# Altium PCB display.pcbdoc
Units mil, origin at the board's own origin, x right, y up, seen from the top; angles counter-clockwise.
Board outline 6129.92 x 2541.69 mil, 2 copper layers (Top Layer, Bottom Layer); 54 components, 77 nets, 200 pads, 30 vias.
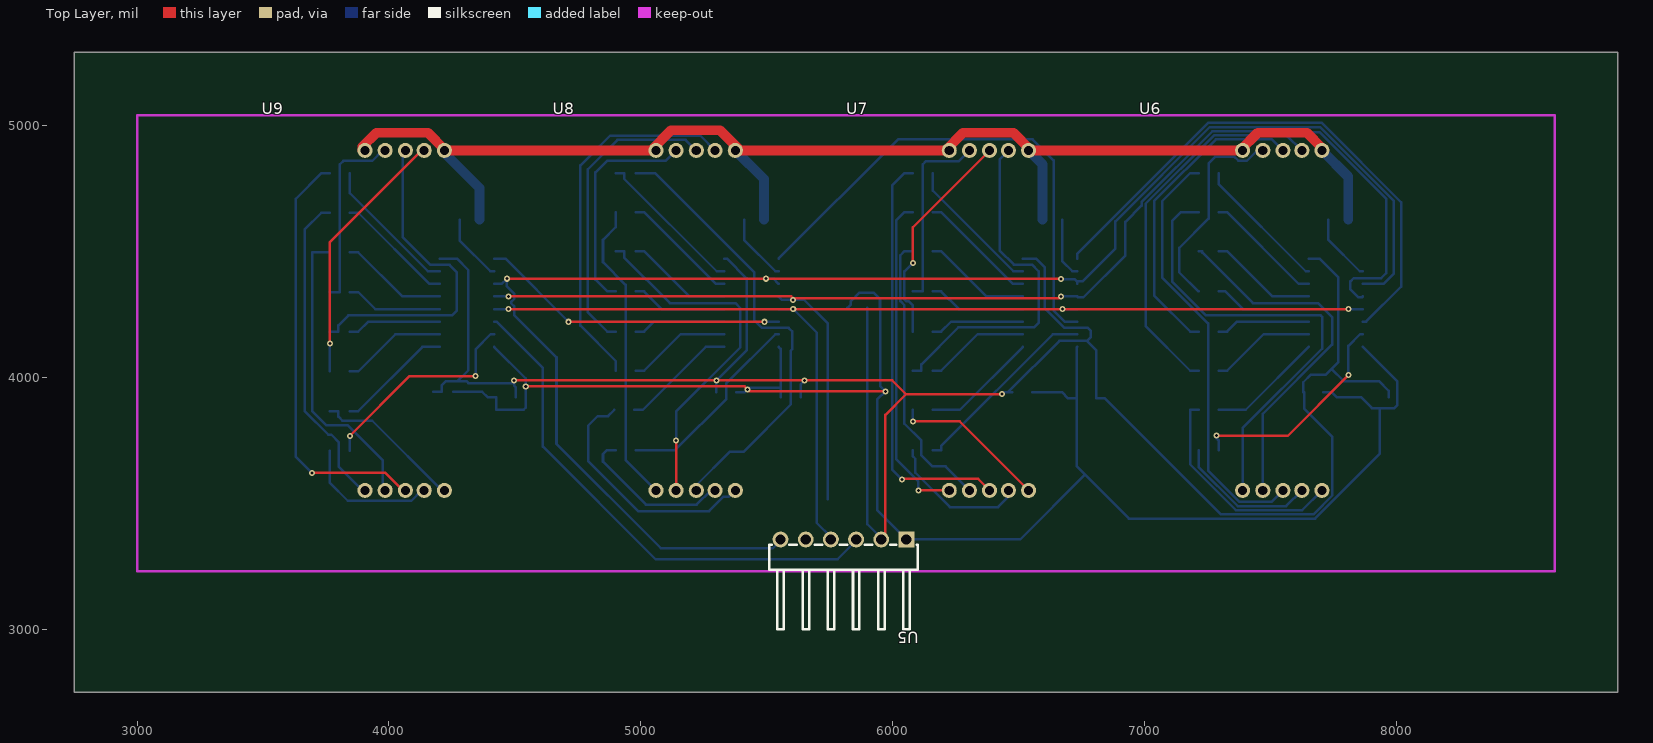
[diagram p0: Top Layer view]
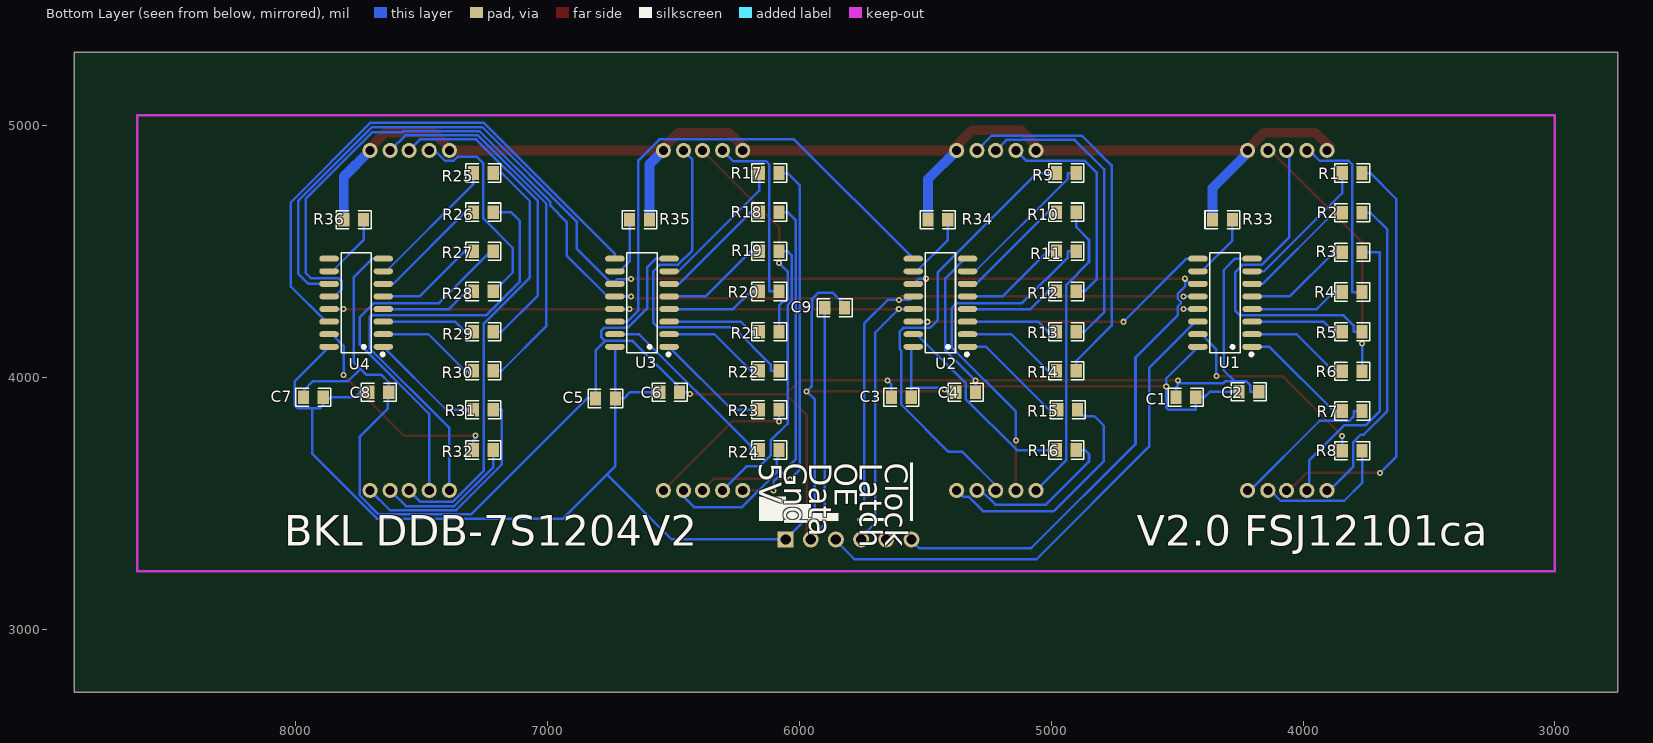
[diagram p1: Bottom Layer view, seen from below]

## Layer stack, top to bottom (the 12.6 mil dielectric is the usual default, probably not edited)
Top Layer: signal copper (thickness not stored)
Dielectric: dielectric 12.6, FR-4, Dk 4.8
Bottom Layer: signal copper (thickness not stored)

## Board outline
8879.92,2750 2750,2750 2750,5291.69 8879.92,5291.69

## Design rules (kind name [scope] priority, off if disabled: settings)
BoardOutlineClearance safeClearance [All] p0: genericclearance=10 ignorepadtopadclearanceinfootprint=FALSE except(0: Arc-SplitContinuation Track-SplitContinuation SMDPad-SplitContinuation THPad-SplitContinuation Via-SplitContinuation Fill-SplitContinuation Poly-SplitContinuation Region-SplitContinuation Text-SplitContinuation; 6: Track-CutoutEdge SMDPad-CutoutEdge THPad-CutoutEdge Via-CutoutEdge Fill-CutoutEdge Region-CutoutEdge; 11.8: Track-OutlineEdge SMDPad-OutlineEdge THPad-OutlineEdge Via-OutlineEdge Fill-OutlineEdge Region-OutlineEdge Poly-OutlineEdge Text-OutlineEdge)
Clearance safeClearance [(InNet('$1N6011') OR InNet('$1N6122') OR InNet('$1N6177') OR InNet('$1N6264') OR InNet('$1N6089') OR InNet('$1N6486') OR InNet('$1N6506') OR InNet('GND') OR InNet('VCC') OR InNet('$1N2299') OR InNet('$1N2304') OR InNet('$1N2303') OR InNet('$1N2305') OR InNet('$1N2301') OR InNet('$1N2297') OR InNet('$1N41012') OR InNet('$1N40781') OR InNet('$1N41044') OR InNet('$1N40619') OR InNet('$1N40652') OR InNet('$1N41427') OR InNet('$1N41428') OR InNet('$1N41338') OR InNet('$1N45600') OR InNet('$1N45601') OR InNet('$1N45602') OR InNet('$1N45596') OR InNet('$1N45606') OR InNet('$1N45595') OR InNet('$1N45598') OR InNet('$1N45607') OR InNet('$1N45594') OR InNet('$1N45609') OR InNet('$1N45599') OR InNet('$1N45603') OR InNet('$1N45597') OR InNet('$1N45604') OR InNet('$1N46576') OR InNet('$1N46577') OR InNet('$1N46584') OR InNet('$1N46585') OR InNet('$1N47561') OR InNet('$1N47562') OR InNet('$1N47571') OR InNet('$1N47559') OR InNet('$1N52982') OR InNet('$1N53020') OR InNet('$1N45593') OR InNet('$1N47985') OR InNet('$1N45605') OR InNet('$1N46581') OR InNet('$1N46582') OR InNet('$1N46583') OR InNet('$1N46587') OR InNet('$1N46579') OR InNet('$1N46588') OR InNet('$1N46575') OR InNet('$1N46590') OR InNet('$1N46580') OR InNet('$1N46578') OR InNet('$1N46574') OR InNet('$1N46586') OR InNet('$1N47566') OR InNet('$1N47567') OR InNet('$1N47568') OR InNet('$1N47572') OR InNet('$1N47564') OR InNet('$1N47573') OR InNet('$1N47560') OR InNet('$1N47575') OR InNet('$1N47565') OR InNet('$1N47569') OR InNet('$1N47563') OR InNet('$1N47570') OR InNet('$1N48013') OR InNet('$1N2302') OR InNet('$1N57025'))] p1: gap=7 ignorepadtopadclearanceinfootprint=FALSE except(6: Track-Track Track-SMDPad SMDPad-SMDPad Track-THPad SMDPad-THPad THPad-THPad Track-Via SMDPad-Via THPad-Via Via-Via Track-Fill SMDPad-Fill THPad-Fill Via-Fill Fill-Fill Track-Region SMDPad-Region THPad-Region Via-Region Fill-Region Region-Region Track-Poly SMDPad-Poly THPad-Poly Via-Poly Fill-Poly Region-Poly Poly-Poly Track-Text SMDPad-Text THPad-Text Via-Text Fill-Text Region-Text Poly-Text Text-Text Track-Hole SMDPad-Hole THPad-Hole Via-Hole Fill-Hole Region-Hole Poly-Hole Text-Hole; 11.8: Track-Sheet SMDPad-Sheet THPad-Sheet Via-Sheet Fill-Sheet Region-Sheet Poly-Sheet Text-Sheet Sheet-Hole)
DiffPairsRouting differentialPair [All] p1: maxuncoupledlength=10 minlimit=6 maxlimit=6 mostfreqgap=6 toplayer_minwidth=5 toplayer_prefwidth=10 toplayer_maxwidth=100 bottomlayer_minwidth=5 bottomlayer_prefwidth=10 bottomlayer_maxwidth=100
PasteMaskExpansion pasteMaskExpansion [All] p1: expansion=0
PlaneConnect innerPlane [All] p1: planeconnectstyle=Relief reliefexpansion=20 reliefentries=4 reliefconductorwidth=10 reliefairgap=10
PolygonConnect copperRegion [All] p1: connectstyle=Relief reliefentries=4 reliefconductorwidth=10 polygonreliefangle="90 Angle" airgapwidth=10
RoutingVias viaSize [All] p1: viastyle="Through Hole" holewidth=12.0078 minholewidth=11.811 maxholewidth=236.2204 width=24.0158 minwidth=19.685 maxwidth=393.7008
SolderMaskExpansion solderMaskExpansion [All] p1: useseparateexpansions=TRUE expansion=2 expansionbottom=2
Width trackWidth [All] p1: maxlimit=100 minlimit=5 preferedwidth=10
Width Vcc [All] p1: maxlimit=100 minlimit=24 preferedwidth=39

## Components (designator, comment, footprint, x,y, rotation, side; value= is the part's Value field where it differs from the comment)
C1 "CR0805J80221G" R0805 4465,3921.69 r0 bottom
C2 "CR0805J80221G" R0805 4215,3943.05 r180 bottom
C3 "CR0805J80221G" R0805 5595,3921.69 r0 bottom
C4 "CR0805J80221G" R0805 5340,3941.69 r180 bottom
C5 "CR0805J80221G" R0805 6770,3916.69 r0 bottom
C6 "CR0805J80221G" R0805 6515,3941.69 r180 bottom
C7 "CR0805J80221G" R0805 7930,3921.69 r0 bottom
C8 "CR0805J80221G" R0805 7670,3941.69 r180 bottom
C9 "CR0805J80221G" R0805 5860,4276.69 r0 bottom
R1 "CR0805J80271G" R0805 3805,4811.69 r0 bottom
R2 "CR0805J80221G" R0805 3805,4654.21 r0 bottom
R3 "CR0805J80221G" R0805 3805,4496.73 r0 bottom
R4 "CR0805J80221G" R0805 3805,4339.25 r0 bottom
R5 "CR0805J80221G" R0805 3805,4181.77 r0 bottom
R6 "CR0805J80221G" R0805 3805,4024.29 r0 bottom
R7 "CR0805J80221G" R0805 3805,3866.81 r0 bottom
R8 "CR0805J80221G" R0805 3805,3709.33 r0 bottom
R9 "CR0805J80271G" R0805 4940,4811.69 r180 bottom
R10 "CR0805J80221G" R0805 4940,4656.69 r0 bottom
R11 "CR0805J80221G" R0805 4940,4501.69 r0 bottom
R12 "CR0805J80221G" R0805 4940,4341.69 r0 bottom
R13 "CR0805J80221G" R0805 4940,4181.69 r0 bottom
R14 "CR0805J80221G" R0805 4940,4026.69 r0 bottom
R15 "CR0805J80221G" R0805 4935,3871.69 r0 bottom
R16 "CR0805J80221G" R0805 4940,3711.69 r0 bottom
R17 "CR0805J80271G" R0805 6120,4811.69 r0 bottom
R18 "CR0805J80221G" R0805 6120,4656.69 r0 bottom
R19 "CR0805J80221G" R0805 6120,4501.69 r0 bottom
R20 "CR0805J80221G" R0805 6120,4341.69 r0 bottom
R21 "CR0805J80221G" R0805 6120,4181.69 r0 bottom
R22 "CR0805J80221G" R0805 6120,4026.69 r0 bottom
R23 "CR0805J80221G" R0805 6120,3871.69 r0 bottom
R24 "CR0805J80221G" R0805 6120,3711.69 r0 bottom
R25 "CR0805J80271G" R0805 7255,4811.69 r0 bottom
R26 "CR0805J80221G" R0805 7255,4656.69 r0 bottom
R27 "CR0805J80221G" R0805 7255,4501.69 r0 bottom
R28 "CR0805J80221G" R0805 7255,4341.69 r0 bottom
R29 "CR0805J80221G" R0805 7255,4181.69 r0 bottom
R30 "CR0805J80221G" R0805 7255,4026.69 r0 bottom
R31 "CR0805J80221G" R0805 7255,3871.69 r0 bottom
R32 "CR0805J80221G" R0805 7255,3711.69 r0 bottom
R33 "CR0805F81002G" R0805 4320,4626.69 r0 bottom
R34 "CR0805F81002G" R0805 5450,4626.69 r0 bottom
R35 "CR0805F81002G" R0805 6635,4626.69 r180 bottom
R36 "CR0805F81002G" R0805 7770,4626.69 r0 bottom
U1 "74HC595D,118" SOIC-16_L9.9-W3.9-P1.27-LS6.0-BL 4310,4296.69 r90 bottom
U2 "74HC595D,118" SOIC-16_L9.9-W3.9-P1.27-LS6.0-BL 5440,4296.69 r90 bottom
U3 "74HC595D,118" SOIC-16_L9.9-W3.9-P1.27-LS6.0-BL 6625,4296.69 r90 bottom
U4 "74HC595D,118" SOIC-16_L9.9-W3.9-P1.27-LS6.0-BL 7760,4296.69 r90 bottom
U5 "P125-1106A0BR138A1" HDR-TH_6P-P2.54-H-M_P125-1106A0BR138A1 5805,3356.69 r180 top
U6 "FJS12101" FJS12101 7550,4226.69 r0 top
U7 "FJS12101" FJS12101 6385,4226.69 r0 top
U8 "FJS12101" FJS12101 5220.32,4226.69 r0 top
U9 "FJS12101" FJS12101 4065,4226.69 r0 top

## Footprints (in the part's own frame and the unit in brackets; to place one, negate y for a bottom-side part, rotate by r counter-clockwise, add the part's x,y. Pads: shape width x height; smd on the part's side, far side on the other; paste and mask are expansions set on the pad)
FJS12101 [mil]
  round 60 hole 36: 1(-160,675) 2(-80,675) 3(0,675) 4(75,675) 5(155,675) 6(155,-675) 7(75,-675) 8(0,-675) 9(-80,-675) 10(-160,-675)
HDR-TH_6P-P2.54-H-M_P125-1106A0BR138A1 [mm]
  rect 1.6x1.6 hole 1.05: 1(-6.35,0)
  round 1.6 hole 1.05: 2(-3.81,0) 3(-1.27,0) 4(1.27,0) 5(3.81,0) 6(6.35,0)
  silkscreen extent -7.47,0.51 7.51,9.06
R0805 [mm]
  rect 1.133x1.377 smd: 1(-1,0) 2(1,0)
  silkscreen extent -1.76,-0.92 1.76,0.92
SOIC-16_L9.9-W3.9-P1.27-LS6.0-BL [mil]
  oval 23.7x77.6 smd: 1(-175,-107.7) 2(-125,-107.7) 3(-75,-107.7) 4(-25,-107.7) 5(25,-107.7) 6(75,-107.7) 7(125,-107.7) 8(175,-107.7) 9(175,107.7) 10(125,107.7) 11(75,107.7) 12(25,107.7) 13(-25,107.7) 14(-75,107.7) 15(-125,107.7) 16(-175,107.7)
  silkscreen extent -211,-111 198,60

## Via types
v1: diameter 24, hole 12, Top Layer to Bottom Layer, 30 vias

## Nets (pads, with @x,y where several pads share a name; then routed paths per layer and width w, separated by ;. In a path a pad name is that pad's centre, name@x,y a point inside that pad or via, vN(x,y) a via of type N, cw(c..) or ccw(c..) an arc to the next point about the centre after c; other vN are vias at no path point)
$1N2297: U1.9 U2.14 | length 1234
  Top Layer w10: v1(4713.6,4221.17) v1(5490.7,4221.17)
  Bottom Layer w10: U1.9 4463.1,4471.67 v1(4713.6,4221.17) ; v1(5490.7,4221.17) 5547.2,4221.17 U2.14
$1N2299: R8.2 U1.15 | length 861.2
  Top Layer w10: v1(3844.4,3767.17) 4082.3,4005.07 v1(4343.7,4005.07)
  Bottom Layer w10: R8.2@3844.4,3709.37 v1(3844.4,3767.17) ; v1(4343.7,4005.07) 4343.7,4111.87 4403.5,4171.67 U1.15
$1N2301: R33.1 U1.10 | length 270.6
  Bottom Layer w10: R33.1 4280.6,4543.67 4402.6,4421.67 U1.10
$1N2302: U1.13 U2.13 U3.13 U4.13 U5.4 | length 4536
  Top Layer w10: v1(4475.2,4271.67) v1(5605.4,4271.67) v1(6675,4271.67) v1(7809.7,4271.67)
  Bottom Layer w10: U1.13 v1(4475.2,4271.67) ; U2.13 v1(5605.4,4271.67) 5698.7,4178.37 5698.7,3422.73 U5.4@5757.37,3364.06 ; v1(6675,4271.67) U3.13 ; v1(7809.7,4271.67) U4.13
$1N2303: U1.12 U2.12 U3.12 U4.12 U5.5 | length 5512.6
  Top Layer w10: v1(4475.1,4322.07) 5596.9,4322.07 v1@5604.2,4314.77 ; v1(5604.2,4307.87) v1@5604.2,4314.77 ; v1(6669.1,4321.77) 6662.2,4314.77 v1@5604.2,4314.77
  Bottom Layer w10: U1.12 4418.1,4322.07 v1(4475.1,4322.07) ; U2.12 5561.5,4307.87 v1(5604.2,4307.87) 5649.2,4307.87 5743,4214.07 5743,3516.69 ; v1(6669.1,4321.77) 6732.7,4321.77 6736.77,4317.7 6757.06,4317.7 6924.56,4485.15 6924.56,4617.9 6989,4682.33 6989,4696.6 7270.07,4977.67 7571.63,4977.67 7575.2,4974.1 7695.74,4974.1 7960,4709.84 7960,4413.97 7940.57,4394.54 7831.29,4394.54 7817.9,4381.16 7817.9,4349.38 7849.59,4317.7 7863.73,4317.7 U4.12
$1N2304: U1.14 U5.3 | length 2027.7
  Bottom Layer w10: U1.14 4427.8,4221.67 4611.2,4038.17 4611.2,3725.49 5058.72,3277.97 5781.28,3277.97 U5.3@5844.98,3341.67
$1N2305: U1.11 U2.11 U3.11 U4.11 U5.6 | length 6330.4
  Top Layer w10: v1(4468,4392.07) v1(5497.1,4392.07) 6668,4392.07 v1(6669.1,4390.87)
  Bottom Layer w10: U1.11 4447.6,4371.67 v1(4468,4392.07) 4468,4361.7 4498.1,4331.6 4498.1,4312.54 4484.73,4299.17 4484.73,4294.67 4498.2,4281.2 4498.2,4246.77 4665.3,4079.67 4665.3,3736.17 5079.8,3321.67 5524.98,3321.67 U5.6@5544.98,3341.67 ; v1(5497.1,4392.07) 5527.3,4392.07 U2.11 ; v1(6669.1,4390.87) 6723.1,4390.87 U3.11@6732.7,4381.27 ; U3.11 U3.11@6732.7,4381.27 ; U4.11 7949.98,4371.67 7990,4411.69 7990,4702.47 7698,4994.47 7259.4,4994.47 6885,4619.88 6885,4511.57 6754.7,4381.27 U3.11@6732.7,4381.27
$1N6011: R7.2 U1.1 | length 463.5
  Bottom Layer w10: R7.2 3878,3866.77 4132.9,4121.67 U1.1
$1N6089: R3.2 U1.5 | length 430.4
  Bottom Layer w10: R3.2@3844.4,4496.77 3878,4496.77 4053.1,4321.67 U1.5
$1N6122: R6.2 U1.2 | length 419
  Bottom Layer w10: R6.2 3878,4024.27 4025.4,4171.67 U1.2
$1N6177: R5.2 U1.3 | length 374.4
  Bottom Layer w10: R5.2 3878,4181.77 3917.9,4221.67 U1.3
$1N6264: R4.2 U1.4 | length 385.9
  Bottom Layer w10: R4.2 3878,4339.27 3945.6,4271.67 U1.4
$1N6486: R2.2 U1.6 | length 474.9
  Bottom Layer w10: R2.2 3878,4654.17 4160.5,4371.67 U1.6
$1N6506: R1.2 U1.7 | length 565.9
  Bottom Layer w10: R1.2 3844.4,4732.29 4155.02,4421.67 U1.7
$1N40619: R8.1 U9.7 | length 539.1
  Bottom Layer w10: R8.1@3765.6,3709.37 3765.6,3581.09 3836.32,3510.37 4088.7,3510.37 U9.7@4130,3551.67
$1N40652: R7.1 U9.6 | length 588.1
  Bottom Layer w10: R7.1 3799.2,3866.77 3799.2,3844.17 3815.5,3827.97 3933.7,3827.97 U9.6@4210,3551.67
$1N40781: R3.1 U9.9 | length 1181.9
  Bottom Layer w10: R3.1@3765.6,4496.77 3695,4496.77 3695,3866.17 3751.4,3809.77 3837.2,3809.77 3975,3671.97 U9.9@3975,3551.67
$1N41012: R2.1 U9.10 | length 1266
  Bottom Layer w10: R2.1 3732,4654.17 3665,4587.17 3665,3866.97 3759.6,3772.37 3771.4,3772.37 3801.4,3742.37 3801.4,3645.27 U9.10@3895,3551.67
$1N41044: R1.1 U9.8 | length 1682.8
  Top Layer w10: v1(3693.8,3621.17) 3985.5,3621.17 U9.8@4055,3551.67
  Bottom Layer w10: v1(3693.8,3621.17) 3630,3684.97 3630,4709.67 3732,4811.67 R1.1
$1N41338: R4.1 U9.2 | length 739.6
  Bottom Layer w10: R4.1 3805,4339.27 3805,4846.69 3818.68,4860.37 3933.7,4860.37 U9.2@3975,4901.67
$1N41427: R6.1 U9.4 | length 1028.3
  Top Layer w10: v1(3765.6,4135.57) 3765.6,4537.27 U9.4@4130,4901.67
  Bottom Layer w10: R6.1 v1(3765.6,4135.57)
$1N41428: R5.1 U9.3 | length 1323
  Bottom Layer w10: R5.1 3799.2,4181.77 3799.2,4206.97 3838.9,4246.67 4250.01,4246.67 4270,4266.7 4270,4417.47 4240.8,4446.67 4164.5,4446.67 4055,4556.27 U9.3@4055,4901.67
$1N45593: R9.2 U2.7 | length 606.4
  Bottom Layer w10: R9.2 4934.2,4811.67 4934.2,4789.17 5301.8,4421.67 U2.7
$1N45594: R12.2 U2.4 | length 381.9
  Bottom Layer w10: R12.2 5013,4341.67 5083,4271.67 U2.4
$1N45595: R14.2 U2.2 | length 413
  Bottom Layer w10: R14.2 5013,4026.67 5158,4171.67 U2.2
$1N45596: R15.2 U2.1 | length 461.5
  Bottom Layer w10: R15.2 5008,3871.67 5258,4121.67 U2.1
$1N45597: R10.2 U2.6 | length 471
  Bottom Layer w10: R10.2 5013,4656.67 5298,4371.67 U2.6
$1N45598: R13.2 U2.3 | length 369.5
  Bottom Layer w10: R13.2 5013,4181.67 5053,4221.67 U2.3
$1N45599: R11.2 U2.5 | length 427.5
  Bottom Layer w10: R11.2 5013,4501.67 5193,4321.67 U2.5
$1N45600: R16.2 U2.15 | length 795.4
  Bottom Layer w10: R16.2 5136.7,3711.67 5340,3915.07 5340,3977.47 5534.3,4171.67 U2.15
$1N45601: R16.1 U8.7 | length 626.7
  Bottom Layer w10: R16.1 4865.6,3711.67 4850,3696.07 4850,3665.57 5020.2,3495.37 5221.98,3495.37 5278.28,3551.67 U8.7
$1N45602: R15.1 U8.6 | length 972.2
  Bottom Layer w10: R15.1 4870.6,3846.67 4829,3846.67 4790.7,3808.37 4790.7,3668.4 4989.73,3469.37 5270.98,3469.37 5328.28,3526.67 5350.3,3526.67 U8.6
$1N45603: R11.1 U8.9 | length 1432.3
  Top Layer w10: U8.9 v1(5140.3,3750.17)
  Bottom Layer w10: R11.1 4934.2,4501.67 4934.2,4476.47 5115.8,4294.87 5375.7,4294.87 5395,4275.8 5395,4119.76 5140.3,3865.17 v1(5140.3,3750.17)
$1N45604: R10.1 U8.10 | length 1213
  Bottom Layer w10: R10.1 4900.6,4597.29 4850,4546.69 4850,4457.81 4940,4367.66 4940,3671.97 U8.10
$1N45605: R9.1 U8.8 | length 1814.4
  Bottom Layer w10: R9.1 5056.5,4811.67 5450,4418.17 5450,4228.47 5481.8,4196.67 5587.4,4196.67 5601.4,4182.67 5601.4,4112.37 5595.7,4106.77 5595.7,3893.05 5407.11,3704.45 5352.76,3704.45 5220.3,3571.99 U8.8
$1N45606: R14.1 U8.4 | length 1481.7
  Bottom Layer w10: R14.1 4900.6,4065.07 4760,4205.84 4760,4841.69 4878.28,4959.97 5237,4959.97 U8.4
$1N45607: R13.1 U8.3 | length 1206.6
  Bottom Layer w10: R13.1 4867,4181.67 4790,4258.44 4790,4826.73 4906.94,4943.57 5178.4,4943.57 U8.3
$1N45609: R12.1 U8.2 | length 882.2
  Bottom Layer w10: R12.1 4867,4341.67 4820,4388.67 4820,4814.4 4865.97,4860.37 5099,4860.37 U8.2
$1N46574: R17.2 U3.7 | length 560.1
  Bottom Layer w10: R17.2 6159.4,4742.29 6480.02,4421.67 U3.7
$1N46575: R20.2 U3.4 | length 386.9
  Bottom Layer w10: R20.2 6193,4341.67 6263,4271.67 U3.4
$1N46576: R22.2 U3.2 | length 418
  Bottom Layer w10: R22.2 6193,4026.67 6338,4171.67 U3.2
$1N46577: R23.2 U3.1 | length 461.5
  Bottom Layer w10: R23.2 6267.3,3871.67 U3.1
$1N46578: R18.2 U3.6 | length 476
  Bottom Layer w10: R18.2 6193,4656.67 6478,4371.67 U3.6
$1N46579: R21.2 U3.3 | length 374.5
  Bottom Layer w10: R21.2 6193,4181.67 6233,4221.67 U3.3
$1N46580: R19.2 U3.5 | length 432.5
  Bottom Layer w10: R19.2 6193,4501.67 6373,4321.67 U3.5
$1N46581: R24.2 U3.15 | length 773.7
  Bottom Layer w10: R24.2 6193,3711.67 6193,3728.47 6636.2,4171.67 U3.15
$1N46582: R24.1 U7.7 | length 562.7
  Bottom Layer w10: R24.1 6080.6,3686.67 6090,3677.27 6090,3622.5 6227.13,3485.37 6419.4,3485.37 6460.7,3526.67 U7.7@6460.7,3551.67
$1N46583: R23.1 U7.6 | length 619.5
  Top Layer w10: v1(6080.6,3825.77) 6266.6,3825.77 U7.6@6540.7,3551.67
  Bottom Layer w10: v1(6080.6,3825.77) R23.1
$1N46584: R19.1 U7.9 | length 1135.3
  Bottom Layer w10: R19.1 6047,4501.67 6030.6,4485.27 6030.6,4303.07 6047,4286.77 6047,3816.07 6114.2,3748.87 6114.2,3690.37 6158,3646.67 6210.7,3646.67 U7.9@6305.7,3551.67
$1N46585: R18.1 U7.10 | length 1311.9
  Top Layer w10: v1(6102.7,3551.67) 6160,3551.67 U7.10@6225.7,3551.67
  Bottom Layer w10: R18.1 6047,4656.67 6014.2,4623.97 6014.2,3675.57 6102.7,3587.17 v1(6102.7,3551.67)
$1N46586: R17.1 U7.8 | length 1655.5
  Top Layer w10: v1(6036.6,3595.07) 6038.8,3597.27 6340.1,3597.27 U7.8@6385.7,3551.67
  Bottom Layer w10: v1(6036.6,3595.07) 5997.9,3633.77 5997.9,4762.57 6047,4811.67 R17.1
$1N46587: R22.1 U7.4 | length 1399
  Bottom Layer w10: R22.1 6114.2,4026.67 6114.2,4051.87 6260.8,4198.47 6561.79,4198.47 6580,4216.76 6580,4421.67 6553.4,4448.27 6481.46,4448.27 6425,4504.73 6425,4865.97 U7.4@6460.7,4901.67
$1N46588: R21.1 U7.3 | length 879.9
  Top Layer w10: v1(6080.6,4454.67) 6080.6,4596.57 U7.3@6385.7,4901.67
  Bottom Layer w10: R21.1 6080.6,4285.97 6063.4,4303.27 6053.6,4303.27 6047,4309.87 6047,4421.07 v1(6080.6,4454.67)
$1N46590: R20.1 U7.2 | length 752.9
  Bottom Layer w10: R20.1 6120,4341.67 6120,4846.75 6132.44,4859.17 6263.2,4859.17 U7.2@6305.7,4901.67
$1N47559: R25.2 U4.7 | length 545
  Bottom Layer w10: R25.2 7294.4,4768.07 7640.8,4421.67 U4.7
$1N47560: R28.2 U4.4 | length 386.9
  Bottom Layer w10: R28.2 7321.2,4341.67 7391.2,4271.67 U4.4
$1N47561: R30.2 U4.2 | length 418
  Bottom Layer w10: R30.2 7328,4026.67 7473,4171.67 U4.2
$1N47562: R31.2 U4.1 | length 461.5
  Bottom Layer w10: R31.2 7402.3,3871.67 U4.1
$1N47563: R26.2 U4.6 | length 476
  Bottom Layer w10: R26.2 7328,4656.67 7613,4371.67 U4.6
$1N47564: R29.2 U4.3 | length 374.5
  Bottom Layer w10: R29.2 7328,4181.67 7368,4221.67 U4.3
$1N47565: R27.2 U4.5 | length 432.5
  Bottom Layer w10: R27.2 7328,4501.67 7508,4321.67 U4.5
$1N47566: R32.2 U4.15 | length 877.7
  Top Layer w10: v1(7285.6,3768.67) 7569.6,3768.67 v1(7810,4009.17)
  Bottom Layer w10: v1(7285.6,3768.67) 7285.6,3758.87 7294.4,3750.07 R32.2 ; v1(7810,4009.17) 7810,4125.37 7856.4,4171.67 U4.15
$1N47567: R32.1 U6.7 | length 566.9
  Bottom Layer w10: R32.1 7215.6,3644.27 7370.7,3489.17 7562.5,3489.17 U6.7
$1N47568: R31.1 U6.6 | length 881.7
  Bottom Layer w10: R31.1 7182,3871.67 7182,3654.57 7363.7,3472.77 7626.1,3472.77 U6.6
$1N47569: R27.1 U6.9 | length 1443.4
  Bottom Layer w10: R27.1 7230,4501.67 7230,4495.67 7430.8,4294.87 7689.8,4294.87 7745,4239.84 7745,4130.47 7470,3855.47 U6.9
$1N47570: R26.1 U6.10 | length 1835.3
  Bottom Layer w10: R26.1 7144.98,4656.67 7110,4621.69 7110,4380.47 7243.8,4246.67 7700.07,4246.67 7706.2,4240.52 7706.2,4114.87 7390,3798.67 U6.10
$1N47571: R25.1 U6.8 | length 1704.9
  Bottom Layer w10: R25.1 7182,4811.67 7070,4699.67 7070,4397.37 7253,4214.37 7253,3630.27 7377.6,3505.67 7504,3505.67 U6.8
$1N47572: R30.1 U6.4 | length 1527.6
  Bottom Layer w10: R30.1 7182,4026.67 7005,4203.67 7005,4689.97 7276.7,4961.67 7565,4961.67 U6.4
$1N47573: R29.1 U6.3 | length 1241.5
  Bottom Layer w10: R29.1 7182,4181.67 7040,4323.67 7040,4701.94 7283.5,4945.27 7506.4,4945.27 U6.3
$1N47575: R28.1 U6.2 | length 839.4
  Bottom Layer w10: R28.1 7214,4341.67 7138.2,4417.47 7138.2,4514.31 7255,4631.11 7255,4849.43 7282.74,4877.17 7356.54,4877.17 7373.02,4860.69 7406.98,4860.69 7447.96,4901.67 U6.2
$1N47985: U2.9 U3.14 | length 2030.9
  Bottom Layer w10: U2.9 6021.5,4945.47 6556.1,4945.47 6639.2,4862.37 6639.2,4265.17 6682.7,4221.67 U3.14
$1N48013: U3.9 U4.14 | length 2196.9
  Bottom Layer w10: U3.9 6732.7,4490.87 7252.6,5010.77 7704.8,5010.77 8020,4695.44 8020,4361.15 7880.7,4221.67 U4.14
$1N52982: R34.1 U2.10 | length 269.2
  Bottom Layer w10: R34.1 5410.6,4546.07 5535,4421.67 U2.10
$1N53020: R36.1 U4.10 | length 269.2
  Bottom Layer w10: R36.1 7730.6,4546.07 7855,4421.67 U4.10
$1N57025: R35.1 U3.10 | length 240.2
  Bottom Layer w10: R35.1 6674.4,4461.07 6713.8,4421.67 U3.10
GND: C1.2 C2.2 C3.2 C4.2 C5.2 C6.2 C7.2 C8.2 C9.2 U1.8 U2.8 U3.8 U4.8 U5.2 | length 9076.3
  Top Layer w10: v1(4497,3987.97) v1(5300.6,3987.97) v1(5650.8,3987.97) 5998.5,3987.97 6053,3933.47 ; U5.2 5960,3356.69 5971.28,3345.42 5971.28,3851.75 6053,3933.47 ; v1(6433.8,3933.47) 6053,3933.47
  Bottom Layer w10: C2.2 4209.2,3943.07 4209.2,3968.27 4226.4,3985.47 4272.7,3985.47 ; U1.8 4270.02,4471.67 4315,4426.69 4315,4027.77 4272.7,3985.47 ; v1(4497,3987.97) v1@4497,3977.77 ; C1.2 4504.4,3960.07 4497,3967.47 v1@4497,3977.77 ; C4.2 v1(5300.6,3987.97) 5420,4107.37 5420,4393.73 5342.2,4471.67 U2.8 ; C3.2 5634.4,3971.57 v1(5650.8,3987.97) ; C9.2 5899.4,3417.29 5955,3361.69 U5.2 ; v1(6433.8,3933.47) 6442,3941.67 C6.2@6458.8,3941.67 ; C6.2 C6.2@6458.8,3941.67 ; U3.8 6569.98,4471.67 6605,4436.73 6605,4273.97 6682.3,4196.67 6775.3,4196.67 6787.1,4184.87 6787.1,4160.07 6772,4144.87 ; C8.2 7635,3941.67 7635,3875.17 7746.8,3763.37 7746.8,3532.27 7670.7,3456.27 7303.4,3456.27 6843,3916.67 C5.2 6809.4,4107.47 6772,4144.87 ; C8.2@7630.62,3966.85 7630.62,3980.99 7661.36,4011.69 7720.72,4011.69 7743.2,4034.17 ; C8.2 C8.2@7630.63,3966.84 ; U4.8 7695.02,4471.67 7770,4396.69 7770,4060.97 7743.2,4034.17 ; C7.2 7969.4,3947.29 7930.82,3985.87 7791.6,3985.87 7743.2,4034.17 ; 4272.7,3985.47 4307.4,3985.47 4315.2,3977.77 v1@4497,3977.77 ; C6.2@6458.8,3941.67 6662,4144.87 6772,4144.87
VCC: C1.1 C2.1 C3.1 C4.1 C5.1 C6.1 C7.1 C8.1 C9.1 R33.2 R34.2 R35.2 R36.2 U1.16 U2.16 U3.16 U4.16 U5.1 U6.1 U6.5 U7.1 U7.5 U8.1 U8.5 U9.1 U9.5 | length 12677.2
  Top Layer w10: v1(4543.2,3964.57) 5412.4,3964.57 v1(5424.1,3952.77) 5431.8,3945.07 v1(5971.1,3945.07)
  Top Layer w39.4: U9.1@3895,4901.67 3895,4916.69 3950,4971.69 4155.06,4971.69 4224.92,4901.67 5039.98,4901.67 5120,4981.69 5315,4981.69 5395.02,4901.67 6160,4901.67 6209.98,4901.67 6280,4971.69 6480,4971.69 6550.02,4901.67 7379.98,4901.67 7450,4971.69 7645,4971.69 7705,4911.69 U6.5
  Bottom Layer w10: C2.1 4370.6,3943.07 4392,3921.67 C1.1 4425.6,3871.69 4534.94,3871.69 4543.2,3879.86 v1(4543.2,3964.57) 4543.2,3996.17 U1.16 ; C4.1 5413,3941.67 v1(5424.1,3952.77) 5431.4,3960.07 5555.6,3960.07 ; U2.16 5555.6,4113.77 5555.6,3960.07 ; C3.1 5555.6,3960.07 ; C9.1 5821.74,4276.67 5834.74,4289.67 5834.74,4302.67 5868.98,4336.69 5925,4336.69 5950,4311.71 5950,4277.27 5951.64,4275.63 5951.64,3964.53 v1(5971.1,3945.07) 5940,3913.97 5940,3471.76 U5.1 6058.18,3356.69 6061.36,3353.51 6064.54,3356.69 6506.92,3356.69 6764.2,3613.97 ; C6.1 6672,3941.67 6697,3916.67 C5.1 ; U3.16 6730.6,4119.57 C5.1 ; C8.1 7743,3941.67 7763,3921.67 7860.02,3921.67 7903.72,3877.97 7934.3,3877.97 ; U4.16 8004.9,3984.47 8004.9,3889.97 7992.9,3877.97 7934.3,3877.97 ; C5.1 6730.6,3647.57 6764.2,3613.97 ; 6764.2,3613.97 6938.3,3439.87 7677.5,3439.87 7934.3,3696.77 7934.3,3877.97
  Bottom Layer w39.4: U9.5@4210,4901.67 4359.4,4752.27 R33.2 ; U8.5 5489.4,4787.57 R34.2 ; U7.5@6540.7,4901.67 6595.6,4846.77 R35.2 ; U6.5 7809.4,4797.27 R36.2
pads on no net: U4.9

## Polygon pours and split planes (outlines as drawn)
VCC on Top Layer (solid, remove dead copper, pour order 0): 3535,4951.69 8125,4951.69 8125,3266.69 3535,3266.69
GND on Bottom Layer (solid, remove dead copper, pour order 2): 3485,4976.69 8150,4976.69 8150,3246.69 3485,3246.69

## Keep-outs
Board Outline Layer:
  lines w10: 3000,3230.67 8629.92,3230.67 8629.92,5041.69 3000,5041.69 3000,3230.67

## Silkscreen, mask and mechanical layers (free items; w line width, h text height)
Bottom Silkscreen Layer:
  region: 5655,3441.69 5768.7,3441.69 5768.7,3430.39 5655,3430.39
  region: 5845,3461.69 5960,3461.69 5960,3431.69 5845,3431.69
  region: 5955,3496.69 6060,3496.69 6060,3431.69 5955,3431.69
  region: 6053.27,3526.61 6160,3526.61 6160,3431.69 6053.27,3431.69
  region: 5550,3661.69 5560,3661.69 5560,3431.69 5550,3431.69
  text "Clock" at 5660,3661.69 h90.55 r90
  text "Latch" at 5760,3661.69 h90.55 r90
  text "OE" at 5860,3661.69 h90.55 r90
  text "Data" at 5960,3661.69 h90.55 r90
  text "Gnd" at 6060,3661.69 h90.55 r90
  text "5V" at 6160,3661.69 h90.55 r90
  text "V2.0 FSJ12101ca" at 4660,3331.69 h120
  text "BKL DDB-7S1204V2" at 8045,3331.69 h120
